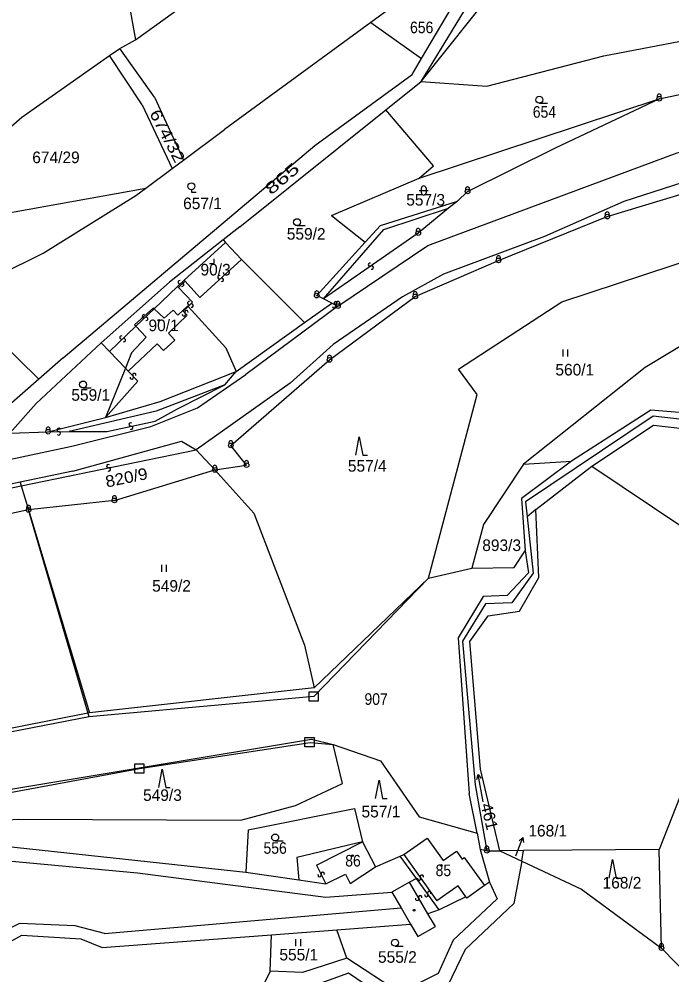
# Model space of a CAD drawing. Extents: x -680102 to -677253, y -1007548 to -1006096.
# Drawn here: x -679300.2 to -679159.4, y -1007036.6 to -1006830.3 of the extents above; entities that cross this region are included whole.
import ezdxf
from ezdxf.enums import TextEntityAlignment as Align

# ---------------------------------------------------------------- set-up
doc = ezdxf.new("R2010")
doc.units = 0
for name, color, linetype, lineweight in [('1', 7, 'Continuous', 25), ('11', 7, 'Continuous', 25), ('13', 7, 'Continuous', 25), ('16', 7, 'Continuous', 25), ('24', 7, 'Continuous', 25), ('25', 7, 'Continuous', 25), ('35', 7, 'Continuous', 25), ('4', 7, 'Continuous', 25)]:
    doc.layers.add(name, color=color, linetype=linetype, lineweight=lineweight)
doc.layers.add('18', color=7, linetype='Continuous')
doc.layers.add('19', color=7, linetype='Continuous')

msp = doc.modelspace()

# ---------------------------------------------------------------- linework, layer by layer
at = {"layer": '1'}
for p, q in [((-679284.21, -1006784.51), (-679275.09, -1006834.83)), ((-679224.33, -1006831.1), (-679213.43, -1006838.82)), ((-679280.73, -1006838.22), (-679278.51, -1006836.66)), ((-679271.02, -1006847.21), (-679278.51, -1006836.66)), ((-679273.66, -1006848.84), (-679280.73, -1006838.22)), ((-679271.02, -1006847.21), (-679264.76, -1006860.76)), ((-679273.66, -1006848.84), (-679267.19, -1006862.56)), ((-679210.85, -1006861.98), (-679221.14, -1006849.93)), ((-679213.97, -1006864.66), (-679210.85, -1006861.98)), ((-679322.48, -1006875.79), (-679272.92, -1006866.8)), ((-679275.08, -1006868.4), (-679272.92, -1006866.8)), ((-679295.03, -1006880.87), (-679275.08, -1006868.4)), ((-679232.81, -1006872.74), (-679225.56, -1006878.51)), ((-679196.82, -1006882.43), (-679173.35, -1006872.96)), ((-679214.79, -1006890.19), (-679196.82, -1006882.43)), ((-679267.81, -1006887.11), (-679282.51, -1006900.22)), ((-679295.97, -1006908.03), (-679314.12, -1006890.25)), ((-679138.35, -1006889.34), (-679165.22, -1006905.55)), ((-679275.31, -1006896.34), (-679271.27, -1006892.66)), ((-679205.48, -1006905.86), (-679183.16, -1006891.35)), ((-679268.97, -1006894.92), (-679266.97, -1006893.19)), ((-679282.51, -1006900.22), (-679296.56, -1006913.3)), ((-679280.75, -1006902.07), (-679282.51, -1006900.22)), ((-679275.98, -1006902.38), (-679272.83, -1006898.96)), ((-679255.61, -1006901.32), (-679253.4, -1006906.37)), ((-679277.3, -1006905.69), (-679281.56, -1006916.35)), ((-679201.39, -1006911.36), (-679205.48, -1006905.86)), ((-679296.56, -1006913.3), (-679302.24, -1006919.69)), ((-679211.91, -1006950.97), (-679201.39, -1006911.36)), ((-679163.98, -1006914.74), (-679181.08, -1006925.74)), ((-679293.97, -1006919.39), (-679281.56, -1006916.35)), ((-679302.24, -1006919.69), (-679293.97, -1006919.39)), ((-679288.67, -1006927.89), (-679265.23, -1006921.46)), ((-679265.23, -1006921.46), (-679262.06, -1006923.28)), ((-679262.06, -1006923.28), (-679258, -1006927.65)), ((-679251.17, -1006926.62), (-679254.56, -1006922.35)), ((-679191.46, -1006926.42), (-679181.08, -1006925.74)), ((-679279.68, -1006934.23), (-679258, -1006927.65)), ((-679258, -1006927.65), (-679251.17, -1006926.62)), ((-679258, -1006927.65), (-679249.59, -1006936.97)), ((-679288.67, -1006927.89), (-679300.01, -1006930.32)), ((-679300.01, -1006930.32), (-679299.77, -1006931.1)), ((-679279.68, -1006934.23), (-679298.19, -1006936.29)), ((-679188.77, -1006936.15), (-679190.65, -1006937.74)), ((-679188.11, -1006950.88), (-679188.77, -1006936.15)), ((-679200.06, -1006939.39), (-679202.6, -1006948.84)), ((-679193.44, -1006948.7), (-679191.04, -1006945.11)), ((-679191.04, -1006945.11), (-679190.34, -1006949.86)), ((-679202.6, -1006948.84), (-679193.44, -1006948.7)), ((-679190.34, -1006949.86), (-679194.92, -1006954.75)), ((-679192.32, -1006958.1), (-679188.11, -1006950.88)), ((-679199.08, -1006959.11), (-679192.32, -1006958.1)), ((-679205.5, -1006963.86), (-679203.17, -1006997.47)), ((-679237.14, -1006985.75), (-679232.46, -1006986.87)), ((-679222.24, -1006990.45), (-679213.91, -1007002.51)), ((-679196.5, -1007009.84), (-679200.7, -1006992.21)), ((-679201.44, -1007006.02), (-679203.17, -1006997.47)), ((-679250.8, -1007005.29), (-679227.9, -1007000.71)), ((-679250.8, -1007005.29), (-679251.29, -1007014.46)), ((-679226.17, -1007007.94), (-679240.32, -1007011.3)), ((-679199.32, -1007009.85), (-679200.77, -1007009.6)), ((-679191.79, -1007012.06), (-679191.45, -1007009.8)), ((-679162.2, -1007009.55), (-679180.98, -1007009.71)), ((-679161.66, -1007030.86), (-679162.2, -1007009.55)), ((-679312.75, -1007011.09), (-679274.67, -1007014.59)), ((-679240.32, -1007011.3), (-679239.92, -1007016.12)), ((-679214.53, -1007015.81), (-679218.01, -1007010.99)), ((-679274.67, -1007014.59), (-679234.06, -1007019.84)), ((-679214.53, -1007015.81), (-679216.03, -1007016.65)), ((-679216.03, -1007016.65), (-679219.81, -1007018.76)), ((-679199.84, -1007017.37), (-679203.63, -1007020.05)), ((-679198.76, -1007016.61), (-679197.13, -1007020.25)), ((-679197.13, -1007020.25), (-679206.61, -1007029.12)), ((-679209.63, -1007022.6), (-679212.03, -1007023.45)), ((-679210.43, -1007026.18), (-679212.03, -1007023.45)), ((-679214.23, -1007028.38), (-679210.43, -1007026.18)), ((-679282.32, -1007030.74), (-679245.76, -1007027.95)), ((-679246.1, -1007035.84), (-679245.76, -1007027.95)), ((-679229.51, -1007032.99), (-679231.72, -1007026.88))]:
    msp.add_line(p, q, dxfattribs=at)
for points in [[(-679213.53, -1006843.82), (-679197.32, -1006823.43), (-679177.95, -1006807.27), (-679162.34, -1006797.04), (-679150.14, -1006784.3)], [(-679213.53, -1006843.82), (-679199.98, -1006821.61), (-679180.43, -1006804.74), (-679162.59, -1006793.01), (-679158.38, -1006786.1)], [(-679184.05, -1006803.4), (-679184.91, -1006802.25), (-679224.33, -1006831.1), (-679255.91, -1006854.2)], [(-679278.51, -1006836.66), (-679275.09, -1006834.83), (-679252.33, -1006818.34)], [(-679215.48, -1006842.32), (-679213.43, -1006838.82), (-679201.67, -1006818.81)], [(-679213.53, -1006843.82), (-679199.32, -1006844.82), (-679174.12, -1006838.27), (-679152.68, -1006834.14)], [(-679329, -1006877.04), (-679299.67, -1006851.48), (-679280.73, -1006838.22)], [(-679162.14, -1006847.54), (-679146.48, -1006844.21), (-679122.51, -1006839.11)], [(-679290.74, -1006903.43), (-679236.46, -1006857.65), (-679215.48, -1006842.32)], [(-679252.64, -1006875.21), (-679221.14, -1006849.93), (-679213.53, -1006843.82)], [(-679232.81, -1006872.74), (-679213.97, -1006864.66), (-679162.14, -1006847.54)], [(-679203.48, -1006867.55), (-679184.56, -1006858.13), (-679162.14, -1006847.54)], [(-679272.92, -1006866.8), (-679267.19, -1006862.56), (-679264.76, -1006860.76), (-679255.91, -1006854.2)], [(-679173.35, -1006872.96), (-679140.72, -1006863.09), (-679107.61, -1006856.01)], [(-679222.29, -1006874.92), (-679205.7, -1006869.6), (-679203.48, -1006867.55)], [(-679183.16, -1006891.35), (-679141.01, -1006877.49), (-679123.69, -1006872.46)], [(-679252.64, -1006875.21), (-679256.2, -1006878), (-679267.81, -1006887.11)], [(-679236.04, -1006890.02), (-679225.56, -1006878.51), (-679222.29, -1006874.92)], [(-679256.2, -1006878), (-679255.7, -1006878.55), (-679252.29, -1006882.26), (-679238.65, -1006895.83)], [(-679315.74, -1006891.05), (-679314.12, -1006890.25), (-679295.03, -1006880.87)], [(-679188.77, -1006936.15), (-679176.67, -1006926.8), (-679163.36, -1006917.97), (-679116.48, -1006923.32), (-679096.46, -1006920.33), (-679086.65, -1006905.68), (-679078.57, -1006900.95), (-679069.87, -1006906.93), (-679064.27, -1006902.32), (-679061.7, -1006885.39)], [(-679254.56, -1006922.35), (-679233.27, -1006903.89), (-679214.79, -1006890.19)], [(-679232.76, -1006891.62), (-679234.59, -1006890.73), (-679236.04, -1006890.02)], [(-679281.56, -1006916.35), (-679269.81, -1006912.9), (-679253.4, -1006906.37), (-679238.65, -1006895.83), (-679232.76, -1006891.62)], [(-679271.27, -1006892.66), (-679271.07, -1006892.86), (-679268.97, -1006894.92)], [(-679266.97, -1006893.19), (-679265.99, -1006894.21), (-679263.87, -1006892.21)], [(-679263.87, -1006892.21), (-679263.75, -1006892.34), (-679255.61, -1006901.32)], [(-679272.83, -1006898.96), (-679275.03, -1006896.63), (-679275.31, -1006896.34)], [(-679275.98, -1006902.38), (-679277.3, -1006905.69), (-679280.75, -1006902.07)], [(-679290.74, -1006903.43), (-679295.97, -1006908.03), (-679303, -1006914.21)], [(-679165.22, -1006905.55), (-679191.46, -1006926.42), (-679200.06, -1006939.39)], [(-679117.02, -1006919.51), (-679131.72, -1006917.41), (-679163.98, -1006914.74)], [(-679181.08, -1006925.74), (-679191.86, -1006933.84), (-679191.04, -1006945.11)], [(-679176.67, -1006926.8), (-679124.12, -1006962.07), (-679049.04, -1006952.79)], [(-679300.01, -1006930.32), (-679332.04, -1006937.15), (-679331.83, -1006937.75), (-679329.93, -1006943.26)], [(-679299.77, -1006931.1), (-679298.19, -1006936.29), (-679285.04, -1006980.07)], [(-679298.19, -1006936.29), (-679326.93, -1006942.43), (-679329.93, -1006943.26)], [(-679249.59, -1006936.97), (-679238.64, -1006965.48), (-679236.56, -1006974.65)], [(-679236.56, -1006974.65), (-679211.91, -1006950.97), (-679202.6, -1006948.84)], [(-679194.92, -1006954.75), (-679200.1, -1006954.98), (-679205.5, -1006963.86)], [(-679200.7, -1006992.21), (-679202.97, -1006964.65), (-679199.08, -1006959.11)], [(-679236.56, -1006974.65), (-679285.04, -1006980.07), (-679315.98, -1006986.21), (-679335.77, -1006991.25)], [(-679143.73, -1006977.4), (-679151.25, -1006981.79), (-679162.2, -1007009.55)], [(-679341.76, -1007005.7), (-679307.68, -1006997.47), (-679237.14, -1006985.75)], [(-679230.44, -1006995.31), (-679232.46, -1006986.87), (-679222.24, -1006990.45)], [(-679341.76, -1007005.7), (-679300.44, -1007003.05), (-679252.42, -1007003.26), (-679240.62, -1007000.1), (-679230.44, -1006995.31)], [(-679227.9, -1007000.71), (-679226.17, -1007007.94), (-679223.32, -1007013.34)], [(-679213.91, -1007002.51), (-679201.44, -1007006.02), (-679200.77, -1007009.6)], [(-679341.76, -1007005.7), (-679308.6, -1007008.25), (-679251.29, -1007014.46)], [(-679217.21, -1007010.64), (-679212.19, -1007007.09), (-679208.75, -1007011.94), (-679205.87, -1007009.9), (-679204.65, -1007011.63), (-679204.21, -1007011.27), (-679199.84, -1007017.37)], [(-679200.77, -1007009.6), (-679198.76, -1007016.61), (-679199.84, -1007017.37)], [(-679180.98, -1007009.71), (-679191.45, -1007009.8), (-679196.5, -1007009.84)], [(-679191.79, -1007012.06), (-679193.5, -1007021.2), (-679203.98, -1007031.12), (-679207.84, -1007039.05), (-679218.17, -1007043.74), (-679229.21, -1007036.25), (-679237.55, -1007039.3), (-679244.37, -1007039.04), (-679249.61, -1007052.13), (-679268.88, -1007058.69), (-679282.87, -1007058.54), (-679292.54, -1007055.79), (-679316.7, -1007056.39), (-679334.5, -1007063.05), (-679344.93, -1007062.85), (-679349.97, -1007067.79), (-679348.09, -1007084.07), (-679355.16, -1007119.77), (-679350.22, -1007135.95), (-679359.5, -1007170.05)], [(-679223.32, -1007013.34), (-679218.01, -1007010.99), (-679217.21, -1007010.64)], [(-679234.07, -1007016.97), (-679229.84, -1007014.86), (-679228.82, -1007016.9), (-679223.32, -1007013.34)], [(-679251.29, -1007014.46), (-679239.92, -1007016.12), (-679234.07, -1007016.97)], [(-679234.06, -1007019.84), (-679219.81, -1007018.76), (-679217.83, -1007022.17)], [(-679203.63, -1007020.05), (-679203.84, -1007019.76), (-679209.63, -1007022.6)], [(-679281.81, -1007027.69), (-679217.83, -1007022.17), (-679215.8, -1007025.67), (-679214.23, -1007028.38)], [(-679281.81, -1007027.69), (-679288.12, -1007026.06), (-679300.13, -1007025.55), (-679317.23, -1007033.9), (-679328.22, -1007036.44), (-679338.3, -1007036.24), (-679352.63, -1007045.79), (-679380.01, -1007071.86), (-679387.43, -1007092.29), (-679392.71, -1007125.35), (-679397.19, -1007140.32), (-679410.92, -1007159.43), (-679421.1, -1007177.36), (-679440.73, -1007187.9), (-679453.05, -1007204.6)], [(-679245.76, -1007027.95), (-679231.72, -1007026.88), (-679215.8, -1007025.67)], [(-679383.65, -1007091.96), (-679377.34, -1007073.15), (-679357.2, -1007054.13), (-679337.25, -1007039.46), (-679329.01, -1007039.46), (-679316.21, -1007037.24), (-679299.62, -1007028.07), (-679286.9, -1007028.88), (-679282.32, -1007030.74)], [(-679206.61, -1007029.12), (-679209.87, -1007036.35), (-679218.11, -1007040.53), (-679229.51, -1007032.99), (-679239.08, -1007036.15), (-679246.1, -1007035.84), (-679253.01, -1007050.06), (-679269.09, -1007055.66), (-679283.65, -1007055.56), (-679288.84, -1007053.53), (-679301.22, -1007053.32), (-679313.23, -1007052.6), (-679335.42, -1007060.85), (-679347.02, -1007060.75), (-679352.61, -1007066.3), (-679351.39, -1007084.13), (-679358.1, -1007120.25), (-679353.32, -1007135.73), (-679361.36, -1007168.26), (-679371.74, -1007181.5)]]:
    msp.add_lwpolyline(points, dxfattribs=at)
at = {"layer": '11'}
for p, q in [((-679236.69, -1006976.57), (-679211.91, -1006950.97)), ((-679307.65, -1006998.26), (-679274.29, -1006992.06))]:
    msp.add_line(p, q, dxfattribs=at)
for points in [[(-679236.69, -1006976.57), (-679285.14, -1006980.92), (-679298.19, -1006936.29)], [(-679285.14, -1006980.92), (-679317.07, -1006987.11), (-679329.93, -1006943.26)], [(-679274.29, -1006992.06), (-679237.43, -1006986.44), (-679232.46, -1006986.87)]]:
    msp.add_lwpolyline(points, dxfattribs=at)
at = {"layer": '13'}
msp.add_line((-679117.37, -1006921.28), (-679163.48, -1006916.03), dxfattribs=at)
for points in [[(-679163.48, -1006916.03), (-679190.98, -1006934.55), (-679190.65, -1006937.74), (-679189.37, -1006949.93), (-679193.97, -1006956.35), (-679199.64, -1006956.56), (-679204.56, -1006964.59), (-679201.89, -1006995.62), (-679199.32, -1007009.85), (-679196.5, -1007009.84), (-679191.79, -1007012.06), (-679178.89, -1007018.13), (-679161.66, -1007030.86)], [(-679161.66, -1007030.86), (-679158.55, -1007034), (-679153.61, -1007038.97)]]:
    msp.add_lwpolyline(points, dxfattribs=at)
at = {"layer": '16'}
for p, q in [((-679192.62, -1007009.77), (-679191.57, -1007006.96)), ((-679193.06, -1007010.95), (-679192.62, -1007009.77))]:
    msp.add_line(p, q, dxfattribs=at)
msp.add_lwpolyline([(-679192.388, -1007007.722), (-679191.57, -1007006.96), (-679191.452, -1007008.072)], dxfattribs=at)
at = {"layer": '24'}
for centre, radius in [((-679162.14, -1006847.54), 0.5), ((-679162.14, -1006847.54), 0.022), ((-679203.48, -1006867.55), 0.5), ((-679203.48, -1006867.55), 0.022), ((-679173.35, -1006872.96), 0.5), ((-679173.35, -1006872.96), 0.022), ((-679214.13, -1006876.54), 0.5), ((-679214.13, -1006876.54), 0.022), ((-679196.82, -1006882.43), 0.5), ((-679196.82, -1006882.43), 0.022), ((-679236.04, -1006890.02), 0.5), ((-679236.04, -1006890.02), 0.022), ((-679214.79, -1006890.19), 0.5), ((-679214.79, -1006890.19), 0.022), ((-679231.46, -1006892.29), 0.5), ((-679231.46, -1006892.29), 0.022), ((-679233.27, -1006903.89), 0.5), ((-679233.27, -1006903.89), 0.022), ((-679293.97, -1006919.39), 0.5), ((-679293.97, -1006919.39), 0.022), ((-679254.56, -1006922.35), 0.5), ((-679254.56, -1006922.35), 0.022), ((-679258, -1006927.65), 0.5), ((-679258, -1006927.65), 0.022), ((-679251.17, -1006926.62), 0.5), ((-679251.17, -1006926.62), 0.022), ((-679279.68, -1006934.23), 0.5), ((-679298.19, -1006936.29), 0.5), ((-679279.68, -1006934.23), 0.022), ((-679298.19, -1006936.29), 0.022), ((-679199.32, -1007009.85), 0.5), ((-679199.32, -1007009.85), 0.022), ((-679161.66, -1007030.86), 0.5), ((-679161.66, -1007030.86), 0.022)]:
    msp.add_circle(centre, radius, dxfattribs=at)
for centre in [(-679162.141, -1006846.977), (-679203.481, -1006866.987), (-679173.351, -1006872.397), (-679214.131, -1006875.977), (-679196.821, -1006881.867), (-679236.041, -1006889.457), (-679214.791, -1006889.627), (-679231.461, -1006891.727), (-679233.271, -1006903.327), (-679293.971, -1006918.827), (-679254.561, -1006921.787), (-679251.171, -1006926.057), (-679258.001, -1006927.087), (-679279.681, -1006933.667), (-679298.191, -1006935.727), (-679199.321, -1007009.287), (-679161.661, -1007030.297)]:
    msp.add_arc(centre, 0.437, 328.35109, 209.97456, dxfattribs=at)
at = {"layer": '25'}
for p, q in [((-679188.02, -1006848.5), (-679186.27, -1006848.5)), ((-679213.96, -1006867.34), (-679211.96, -1006867.34)), ((-679213.46, -1006867.84), (-679213.46, -1006866.84)), ((-679212.46, -1006866.84), (-679212.46, -1006867.84)), ((-679240.26, -1006874.92), (-679238.51, -1006874.92)), ((-679182.897, -1006903.155), (-679182.897, -1006901.655)), ((-679181.863, -1006903.155), (-679181.863, -1006901.655)), ((-679286.43, -1006909.95), (-679284.68, -1006909.95)), ((-679269.477, -1006949.655), (-679269.477, -1006948.155)), ((-679268.443, -1006949.655), (-679268.443, -1006948.155)), ((-679200.119, -1006999.258), (-679201.221, -1006993.362)), ((-679245, -1007007.73), (-679243.25, -1007007.73)), ((-679240.517, -1007030.415), (-679240.517, -1007028.915)), ((-679239.483, -1007030.415), (-679239.483, -1007028.915)), ((-679219.13, -1007030.45), (-679217.38, -1007030.45))]:
    msp.add_line(p, q, dxfattribs=at)
for points in [[(-679263.06, -1006867.17), (-679263.06, -1006867.67), (-679262.037, -1006867.67)], [(-679259.16, -1006883.09), (-679258.16, -1006883.09), (-679258.16, -1006882.09)], [(-679227.61, -1006924.48), (-679226.86, -1006920.48), (-679226.11, -1006924.48), (-679225.11, -1006924.48)], [(-679270.11, -1006996.21), (-679269.36, -1006992.21), (-679268.61, -1006996.21), (-679267.61, -1006996.21)], [(-679201.529, -1006994.437), (-679201.221, -1006993.362), (-679200.547, -1006994.253)], [(-679223.34, -1006998.57), (-679222.59, -1006994.57), (-679221.84, -1006998.57), (-679220.84, -1006998.57)], [(-679172.95, -1007015.74), (-679172.2, -1007011.74), (-679171.45, -1007015.74), (-679170.45, -1007015.74)]]:
    msp.add_lwpolyline(points, dxfattribs=at)
for centre, radius in [((-679188.02, -1006847.75), 0.75), ((-679263.06, -1006866.42), 0.75), ((-679240.26, -1006874.17), 0.75), ((-679270.08, -1006895.36), 0.175), ((-679286.43, -1006909.2), 0.75), ((-679245, -1007006.98), 0.75), ((-679228.31, -1007010.89), 0.175), ((-679209.17, -1007013.01), 0.175), ((-679215.02, -1007022.67), 0.175), ((-679219.13, -1007029.7), 0.75)]:
    msp.add_circle(centre, radius, dxfattribs=at)
for centre, radius, start, end in [((-679212.96, -1006866.84), 0.5, 0.101, 180.00143), ((-679212.96, -1006867.84), 0.5, 180.10243, 0.00286), ((-679224.567, -1006883.335), 0.369, 72.00749, 303.85092), ((-679224.153, -1006883.944), 0.368, 251.42438, 124.25276), ((-679256.995, -1006886.065), 0.369, 79.84865, 311.62479), ((-679256.504, -1006886.613), 0.368, 259.52473, 132.02303), ((-679265.57, -1006887.12), 0.368, 80.79376, 312.71924), ((-679265.069, -1006887.659), 0.368, 260.2837, 133.01853), ((-679263.542, -1006891.631), 0.369, 80.94721, 312.78449), ((-679263.038, -1006892.168), 0.368, 260.62819, 133.23867), ((-679232.282, -1006892.286), 0.368, 190.00049, 61.96118), ((-679231.939, -1006891.635), 0.368, 10.14136, 242.25065), ((-679273.3, -1006894.48), 0.368, 80.79376, 312.71924), ((-679272.799, -1006895.019), 0.368, 260.2837, 133.01853), ((-679264.681, -1006894.07), 0.369, 170.48799, 42.42743), ((-679264.141, -1006893.57), 0.368, 350.4137, 222.90517), ((-679278.14, -1006899.08), 0.368, 80.79376, 312.71924), ((-679277.639, -1006899.619), 0.368, 260.2837, 133.01853), ((-679275.38, -1006907.169), 0.369, 350.79591, 223.183), ((-679275.918, -1006907.672), 0.368, 170.83607, 43.23795), ((-679276.173, -1006917.85), 0.367, 49.18961, 281.46512), ((-679291.689, -1006919.013), 0.367, 37.82221, 269.84603), ((-679291.693, -1006919.748), 0.368, 217.8358, 89.78737), ((-679276.028, -1006918.571), 0.369, 229.40053, 101.5534), ((-679280.992, -1006926.829), 0.368, 48.82788, 281.28164), ((-679280.849, -1006927.551), 0.368, 229.18139, 101.13034), ((-679234.74, -1007014.808), 0.368, 333.59993, 206.14848), ((-679235.402, -1007015.131), 0.369, 154.13064, 25.94159), ((-679213.963, -1007015.87), 0.369, 162.4991, 34.45168), ((-679213.358, -1007015.45), 0.367, 342.46689, 214.81508), ((-679214.349, -1007020.234), 0.368, 158.04347, 29.97669), ((-679213.71, -1007019.867), 0.369, 337.68173, 210.04708), ((-679212.379, -1007019.423), 0.368, 163.08097, 35.46539), ((-679211.779, -1007018.998), 0.369, 343.13982, 215.39387)]:
    msp.add_arc(centre, radius, start, end, dxfattribs=at)
at = {"layer": '35'}
for points in [[(-679237.69, -1006975.57), (-679235.69, -1006975.57), (-679235.69, -1006977.57), (-679237.69, -1006977.57)], [(-679238.59, -1006985.39), (-679236.59, -1006985.39), (-679236.59, -1006987.39), (-679238.59, -1006987.39)], [(-679275.29, -1006991.06), (-679273.29, -1006991.06), (-679273.29, -1006993.06), (-679275.29, -1006993.06)]]:
    msp.add_lwpolyline(points, close=True, dxfattribs=at)
at = {"layer": '4'}
for p, q in [((-679221.54, -1006875.74), (-679207.62, -1006871.18)), ((-679231.46, -1006892.29), (-679212.08, -1006879.19)), ((-679264.61, -1006886.71), (-679266.04, -1006888.07)), ((-679266.04, -1006888.07), (-679265.83, -1006888.29)), ((-679265.83, -1006888.29), (-679264.41, -1006886.93)), ((-679265.83, -1006888.29), (-679262.82, -1006891.45)), ((-679263.75, -1006892.34), (-679264.83, -1006893.37)), ((-679262.82, -1006891.45), (-679263.75, -1006892.34)), ((-679276.67, -1006906.35), (-679277.3, -1006905.69)), ((-679274.63, -1006908.49), (-679276.67, -1006906.35)), ((-679261.74, -1006914.21), (-679251.3, -1006907.07)), ((-679255.83, -1006909.29), (-679253.4, -1006906.37)), ((-679281.56, -1006916.35), (-679274.63, -1006908.49)), ((-679270.64, -1006914.97), (-679289.4, -1006919.36)), ((-679299.77, -1006931.1), (-679262.06, -1006923.28)), ((-679236.08, -1007012.97), (-679226.17, -1007007.94)), ((-679217.21, -1007010.64), (-679210.1, -1007020.68)), ((-679236.08, -1007012.97), (-679234.07, -1007016.97)), ((-679209.63, -1007022.6), (-679214.53, -1007015.81)), ((-679212.03, -1007023.45), (-679216.03, -1007016.65)), ((-679205.49, -1007017.42), (-679210.1, -1007020.68)), ((-679203.84, -1007019.76), (-679205.49, -1007017.42))]:
    msp.add_line(p, q, dxfattribs=at)
for points in [[(-679212.08, -1006879.19), (-679158.26, -1006859.18), (-679115.37, -1006849.13), (-679087.19, -1006840.79), (-679070.52, -1006831.96), (-678996.84, -1006759.45)], [(-679074.69, -1006843.49), (-679089.37, -1006848.62), (-679108, -1006853.77), (-679140.1, -1006860.15), (-679169.76, -1006869.71), (-679186.89, -1006877.28), (-679208.7, -1006885.37), (-679217.52, -1006890.28), (-679232.47, -1006900.58), (-679241.78, -1006908.92), (-679262.06, -1006923.28)], [(-679205.7, -1006869.6), (-679207.62, -1006871.18), (-679214.13, -1006876.54)], [(-679214.13, -1006876.54), (-679234.59, -1006890.73), (-679221.54, -1006875.74)], [(-679252.29, -1006882.26), (-679261.21, -1006890.42), (-679264.41, -1006886.93), (-679264.61, -1006886.71), (-679255.7, -1006878.55)], [(-679266.04, -1006888.07), (-679271.07, -1006892.86), (-679275.03, -1006896.63), (-679280.75, -1006902.07)], [(-679232.76, -1006891.62), (-679231.46, -1006892.29), (-679251.3, -1006907.07)], [(-679264.83, -1006893.37), (-679263.98, -1006894.27), (-679268.04, -1006898.13), (-679266.64, -1006899.6), (-679269.06, -1006901.89), (-679270.45, -1006900.43), (-679276.67, -1006906.35)], [(-679281.29, -1006919.32), (-679270.91, -1006917.1), (-679266.03, -1006914.44), (-679255.83, -1006909.29), (-679270.64, -1006914.97)], [(-679583.52, -1007075.61), (-679568.28, -1007070.4), (-679510.15, -1007046.23), (-679492.51, -1007036.77), (-679474.86, -1007019.28), (-679449.4, -1006974.77), (-679431.68, -1006958.02), (-679426.67, -1006954.59), (-679411.66, -1006948.44), (-679396.57, -1006943.87), (-679372.18, -1006940.28), (-679288.86, -1006922.55), (-679271.84, -1006918.25), (-679261.74, -1006914.21)], [(-679293.97, -1006919.39), (-679289.4, -1006919.36), (-679281.29, -1006919.32)], [(-679401.81, -1006952.27), (-679331.83, -1006937.75), (-679299.77, -1006931.1)]]:
    msp.add_lwpolyline(points, dxfattribs=at)

# ---------------------------------------------------------------- texts
at = {"layer": '16'}
msp.add_text('168/1', height=2.5, dxfattribs=at).set_placement((-679190.38, -1007006.76))
at = {"layer": '18', "width": 0.9}
for s, p in [('656', (-679215.9, -1006833.38)), ('654', (-679189.43, -1006851.62))]:
    msp.add_text(s, height=2.5, dxfattribs=at).set_placement(p)
at = {"layer": '18'}
for s, rotation, width, p in [('674/32', 297.302, 1.2, (-679272.171, -1006850.685)), ('865', 40.3, 1.5, (-679245.877, -1006868.429)), ('820/9', 11.7, 1.1, (-679281.325, -1006931.444)), ('461', 283.602, 1.05, (-679200.699, -1006999.877))]:
    msp.add_text(s, height=2.5, rotation=rotation, dxfattribs=dict(at, width=width)).set_placement(p)
for s, height, p in [('674/29', 2.5, (-679297.39, -1006861.43)), ('557/3', 2.5, (-679216.72, -1006870.59)), ('657/1', 2.5, (-679264.85, -1006871.36)), ('559/2', 2.5, (-679242.49, -1006877.94)), ('560/1', 2.5, (-679184.55, -1006907.26)), ('559/1', 2.5, (-679288.96, -1006912.71)), ('557/4', 2.5, (-679229.31, -1006928.01)), ('549/2', 2.5, (-679271.53, -1006953.92)), ('168/1', 0.1, (-679192.86, -1007010.75)), ('168/2', 2.5, (-679174.37, -1007017.99))]:
    msp.add_text(s, height=height, dxfattribs=at).set_placement(p)
for s, p in [('893/3', (-679196.14, -1006945.15)), ('549/3', (-679269.309, -1006999.08)), ('557/1', (-679222.189, -1007002.64)), ('555/1', (-679239.9, -1007033.51)), ('555/2', (-679218.63, -1007034.02))]:
    msp.add_text(s, height=2.5, dxfattribs=at).set_placement(p, align=Align.CENTER)
at = {"layer": '18', "width": 0.9}
for s, p in [('907', (-679223.22, -1006978.35)), ('556', (-679245, -1007010.49))]:
    msp.add_text(s, height=2.5, dxfattribs=at).set_placement(p, align=Align.CENTER)
at = {"layer": '19'}
for s, p in [('90/3', (-679261.1, -1006885.67)), ('90/1', (-679272.32, -1006897.69))]:
    msp.add_text(s, height=2.5, dxfattribs=at).set_placement(p)
at = {"layer": '19', "width": 0.9}
msp.add_text('86', height=2.5, dxfattribs=at).set_placement((-679228.209, -1007013.24), align=Align.CENTER)
msp.add_text('85', height=2.5, dxfattribs=at).set_placement((-679210.39, -1007015.32))

doc.saveas('drawing.dxf')
